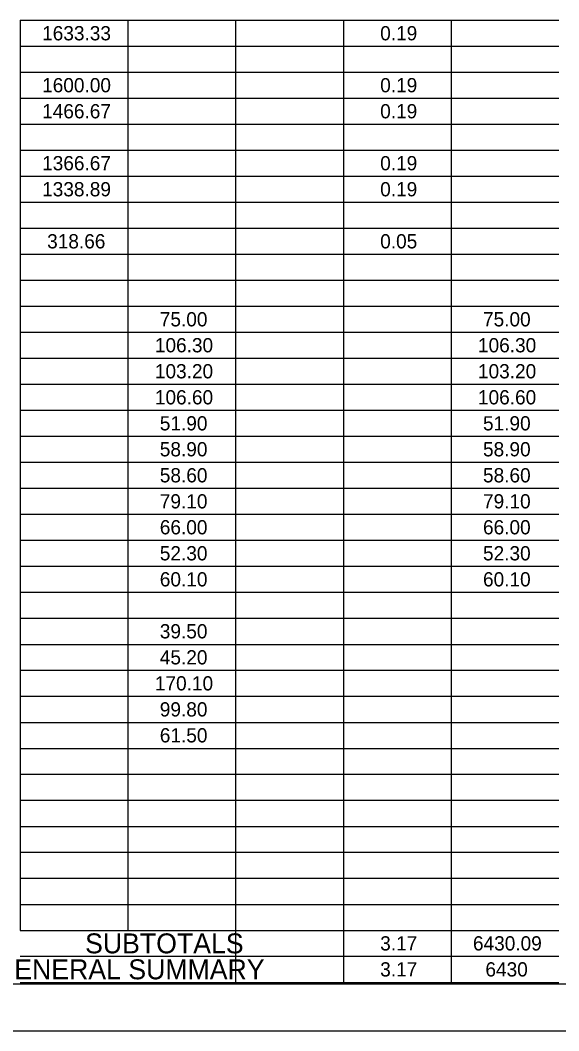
# Model space of a CAD drawing. Extents: x 0 to 34, y 0 to 22.
# Drawn here: x 10.58 to 16.38, y 0 to 10.87 of the extents above; entities that cross this region are included whole.
import ezdxf

# ---------------------------------------------------------------- set-up
doc = ezdxf.new("R2010")
doc.units = 0
for name, color, linetype in [('SH_Border', 7, 'Continuous'), ('SH_Cut_Line', 7, 'Continuous'), ('SH_Text', 7, 'Continuous')]:
    doc.layers.add(name, color=color, linetype=linetype)

msp = doc.modelspace()

# ---------------------------------------------------------------- linework, layer by layer
at = {"layer": 'SH_Border'}
msp.add_lwpolyline([(1.5, 21.5), (33.5, 21.5), (33.5, 0.5), (1.5, 0.5)], close=True, dxfattribs=at)
at = {"layer": 'SH_Cut_Line'}
msp.add_lwpolyline([(0, 0), (34, 0), (34, 22), (0, 22)], close=True, dxfattribs=at)
at = {"layer": 'SH_Text'}
for p, q in [((10.584, 10.871), (11.743, 10.871)), ((10.584, 10.871), (10.584, 10.591)), ((11.743, 10.871), (14.061, 10.871)), ((11.743, 10.871), (11.743, 10.591)), ((12.902, 10.871), (12.902, 10.591)), ((14.061, 10.871), (15.22, 10.871)), ((14.061, 10.871), (14.061, 10.591)), ((15.22, 10.871), (16.378, 10.871)), ((15.22, 10.871), (15.22, 10.591)), ((10.584, 10.591), (11.743, 10.591)), ((10.584, 10.591), (10.584, 10.311)), ((11.743, 10.591), (14.061, 10.591)), ((11.743, 10.591), (11.743, 10.311)), ((12.902, 10.591), (12.902, 10.311)), ((14.061, 10.591), (15.22, 10.591)), ((14.061, 10.591), (14.061, 10.311)), ((15.22, 10.591), (16.378, 10.591)), ((15.22, 10.591), (15.22, 10.311)), ((10.584, 10.311), (11.743, 10.311)), ((10.584, 10.311), (10.584, 10.031)), ((11.743, 10.311), (14.061, 10.311)), ((11.743, 10.311), (11.743, 10.031)), ((12.902, 10.311), (12.902, 10.031)), ((14.061, 10.311), (15.22, 10.311)), ((14.061, 10.311), (14.061, 10.031)), ((15.22, 10.311), (16.378, 10.311)), ((15.22, 10.311), (15.22, 10.031)), ((10.584, 10.031), (11.743, 10.031)), ((10.584, 10.031), (10.584, 9.752)), ((11.743, 10.031), (14.061, 10.031)), ((11.743, 10.031), (11.743, 9.752)), ((12.902, 10.031), (12.902, 9.752)), ((14.061, 10.031), (15.22, 10.031)), ((14.061, 10.031), (14.061, 9.752)), ((15.22, 10.031), (16.378, 10.031)), ((15.22, 10.031), (15.22, 9.752)), ((10.584, 9.752), (11.743, 9.752)), ((10.584, 9.752), (10.584, 9.472)), ((11.743, 9.752), (14.061, 9.752)), ((11.743, 9.752), (11.743, 9.472)), ((12.902, 9.752), (12.902, 9.472)), ((14.061, 9.752), (15.22, 9.752)), ((14.061, 9.752), (14.061, 9.472)), ((15.22, 9.752), (16.378, 9.752)), ((15.22, 9.752), (15.22, 9.472)), ((10.584, 9.472), (11.743, 9.472)), ((10.584, 9.472), (10.584, 9.192)), ((11.743, 9.472), (14.061, 9.472)), ((11.743, 9.472), (11.743, 9.192)), ((12.902, 9.472), (12.902, 9.192)), ((14.061, 9.472), (15.22, 9.472)), ((14.061, 9.472), (14.061, 9.192)), ((15.22, 9.472), (16.378, 9.472)), ((15.22, 9.472), (15.22, 9.192)), ((10.584, 9.192), (11.743, 9.192)), ((10.584, 9.192), (10.584, 8.913)), ((11.743, 9.192), (14.061, 9.192)), ((11.743, 9.192), (11.743, 8.913)), ((12.902, 9.192), (12.902, 8.913)), ((14.061, 9.192), (15.22, 9.192)), ((14.061, 9.192), (14.061, 8.913)), ((15.22, 9.192), (16.378, 9.192)), ((15.22, 9.192), (15.22, 8.913)), ((10.584, 8.913), (11.743, 8.913)), ((10.584, 8.913), (10.584, 8.633)), ((11.743, 8.913), (14.061, 8.913)), ((11.743, 8.913), (11.743, 8.633)), ((12.902, 8.913), (12.902, 8.633)), ((14.061, 8.913), (15.22, 8.913)), ((14.061, 8.913), (14.061, 8.633)), ((15.22, 8.913), (16.378, 8.913)), ((15.22, 8.913), (15.22, 8.633)), ((10.584, 8.633), (11.743, 8.633)), ((10.584, 8.633), (10.584, 8.353)), ((11.743, 8.633), (14.061, 8.633)), ((11.743, 8.633), (11.743, 8.353)), ((12.902, 8.633), (12.902, 8.353)), ((14.061, 8.633), (15.22, 8.633)), ((14.061, 8.633), (14.061, 8.353)), ((15.22, 8.633), (16.378, 8.633)), ((15.22, 8.633), (15.22, 8.353)), ((10.584, 8.353), (11.743, 8.353)), ((10.584, 8.353), (10.584, 8.073)), ((11.743, 8.353), (14.061, 8.353)), ((11.743, 8.353), (11.743, 8.073)), ((12.902, 8.353), (12.902, 8.073)), ((14.061, 8.353), (15.22, 8.353)), ((14.061, 8.353), (14.061, 8.073)), ((15.22, 8.353), (16.378, 8.353)), ((15.22, 8.353), (15.22, 8.073)), ((10.584, 8.073), (11.743, 8.073)), ((10.584, 8.073), (10.584, 7.794)), ((11.743, 8.073), (14.061, 8.073)), ((11.743, 8.073), (11.743, 7.794)), ((12.902, 8.073), (12.902, 7.794)), ((14.061, 8.073), (15.22, 8.073)), ((14.061, 8.073), (14.061, 7.794)), ((15.22, 8.073), (16.378, 8.073)), ((15.22, 8.073), (15.22, 7.794)), ((10.584, 7.794), (11.743, 7.794)), ((10.584, 7.794), (10.584, 7.514)), ((11.743, 7.794), (14.061, 7.794)), ((11.743, 7.794), (11.743, 7.514)), ((12.902, 7.794), (12.902, 7.514)), ((14.061, 7.794), (15.22, 7.794)), ((14.061, 7.794), (14.061, 7.514)), ((15.22, 7.794), (16.378, 7.794)), ((15.22, 7.794), (15.22, 7.514)), ((10.584, 7.514), (11.743, 7.514)), ((10.584, 7.514), (10.584, 7.234)), ((11.743, 7.514), (14.061, 7.514)), ((11.743, 7.514), (11.743, 7.234)), ((12.902, 7.514), (12.902, 7.234)), ((14.061, 7.514), (15.22, 7.514)), ((14.061, 7.514), (14.061, 7.234)), ((15.22, 7.514), (16.378, 7.514)), ((15.22, 7.514), (15.22, 7.234)), ((10.584, 7.234), (11.743, 7.234)), ((10.584, 7.234), (10.584, 6.955)), ((11.743, 7.234), (14.061, 7.234)), ((11.743, 7.234), (11.743, 6.955)), ((12.902, 7.234), (12.902, 6.955)), ((14.061, 7.234), (15.22, 7.234)), ((14.061, 7.234), (14.061, 6.955)), ((15.22, 7.234), (16.378, 7.234)), ((15.22, 7.234), (15.22, 6.955)), ((10.584, 6.955), (11.743, 6.955)), ((10.584, 6.955), (10.584, 6.675)), ((11.743, 6.955), (14.061, 6.955)), ((11.743, 6.955), (11.743, 6.675)), ((12.902, 6.955), (12.902, 6.675)), ((14.061, 6.955), (15.22, 6.955)), ((14.061, 6.955), (14.061, 6.675)), ((15.22, 6.955), (16.378, 6.955)), ((15.22, 6.955), (15.22, 6.675)), ((10.584, 6.675), (11.743, 6.675)), ((10.584, 6.675), (10.584, 6.395)), ((11.743, 6.675), (14.061, 6.675)), ((11.743, 6.675), (11.743, 6.395)), ((12.902, 6.675), (12.902, 6.395)), ((14.061, 6.675), (15.22, 6.675)), ((14.061, 6.675), (14.061, 6.395)), ((15.22, 6.675), (16.378, 6.675)), ((15.22, 6.675), (15.22, 6.395)), ((10.584, 6.395), (11.743, 6.395)), ((10.584, 6.395), (10.584, 6.115)), ((11.743, 6.395), (14.061, 6.395)), ((11.743, 6.395), (11.743, 6.115)), ((12.902, 6.395), (12.902, 6.115)), ((14.061, 6.395), (15.22, 6.395)), ((14.061, 6.395), (14.061, 6.115)), ((15.22, 6.395), (16.378, 6.395)), ((15.22, 6.395), (15.22, 6.115)), ((10.584, 6.115), (11.743, 6.115)), ((10.584, 6.115), (10.584, 5.836)), ((11.743, 6.115), (14.061, 6.115)), ((11.743, 6.115), (11.743, 5.836)), ((12.902, 6.115), (12.902, 5.836)), ((14.061, 6.115), (15.22, 6.115)), ((14.061, 6.115), (14.061, 5.836)), ((15.22, 6.115), (16.378, 6.115)), ((15.22, 6.115), (15.22, 5.836)), ((10.584, 5.836), (11.743, 5.836)), ((10.584, 5.836), (10.584, 5.276)), ((11.743, 5.836), (14.061, 5.836)), ((11.743, 5.836), (11.743, 5.276)), ((12.902, 5.836), (12.902, 5.276)), ((14.061, 5.836), (15.22, 5.836)), ((14.061, 5.836), (14.061, 5.276)), ((15.22, 5.836), (16.378, 5.836)), ((15.22, 5.836), (15.22, 5.276)), ((10.584, 5.556), (11.743, 5.556)), ((11.743, 5.556), (14.061, 5.556)), ((14.061, 5.556), (15.22, 5.556)), ((15.22, 5.556), (16.378, 5.556)), ((10.584, 5.276), (11.743, 5.276)), ((10.584, 5.276), (10.584, 4.997)), ((11.743, 5.276), (14.061, 5.276)), ((11.743, 5.276), (11.743, 4.997)), ((12.902, 5.276), (12.902, 4.997)), ((14.061, 5.276), (15.22, 5.276)), ((14.061, 5.276), (14.061, 4.997)), ((15.22, 5.276), (16.378, 5.276)), ((15.22, 5.276), (15.22, 4.997)), ((10.584, 4.997), (11.743, 4.997)), ((10.584, 4.997), (10.584, 4.717)), ((11.743, 4.997), (14.061, 4.997)), ((11.743, 4.997), (11.743, 4.717)), ((12.902, 4.997), (12.902, 4.717)), ((14.061, 4.997), (15.22, 4.997)), ((14.061, 4.997), (14.061, 4.717)), ((15.22, 4.997), (16.378, 4.997)), ((15.22, 4.997), (15.22, 4.717)), ((10.584, 4.717), (11.743, 4.717)), ((10.584, 4.717), (10.584, 4.437)), ((11.743, 4.717), (14.061, 4.717)), ((11.743, 4.717), (11.743, 4.437)), ((12.902, 4.717), (12.902, 4.437)), ((14.061, 4.717), (15.22, 4.717)), ((14.061, 4.717), (14.061, 4.437)), ((15.22, 4.717), (16.378, 4.717)), ((15.22, 4.717), (15.22, 4.437)), ((10.584, 4.437), (11.743, 4.437)), ((10.584, 4.437), (10.584, 3.878)), ((11.743, 4.437), (14.061, 4.437)), ((11.743, 4.437), (11.743, 3.878)), ((12.902, 4.437), (12.902, 3.878)), ((14.061, 4.437), (15.22, 4.437)), ((14.061, 4.437), (14.061, 3.878)), ((15.22, 4.437), (16.378, 4.437)), ((15.22, 4.437), (15.22, 3.878)), ((10.584, 4.157), (11.743, 4.157)), ((11.743, 4.157), (14.061, 4.157)), ((14.061, 4.157), (15.22, 4.157)), ((15.22, 4.157), (16.378, 4.157)), ((10.584, 3.878), (11.743, 3.878)), ((10.584, 3.878), (10.584, 3.598)), ((11.743, 3.878), (14.061, 3.878)), ((11.743, 3.878), (11.743, 3.598)), ((12.902, 3.878), (12.902, 3.598)), ((14.061, 3.878), (15.22, 3.878)), ((14.061, 3.878), (14.061, 3.598)), ((15.22, 3.878), (16.378, 3.878)), ((15.22, 3.878), (15.22, 3.598)), ((10.584, 3.598), (11.743, 3.598)), ((10.584, 3.598), (10.584, 3.318)), ((11.743, 3.598), (14.061, 3.598)), ((11.743, 3.598), (11.743, 3.318)), ((12.902, 3.598), (12.902, 3.318)), ((14.061, 3.598), (15.22, 3.598)), ((14.061, 3.598), (14.061, 3.318)), ((15.22, 3.598), (16.378, 3.598)), ((15.22, 3.598), (15.22, 3.318)), ((10.584, 3.318), (11.743, 3.318)), ((10.584, 3.318), (10.584, 3.038)), ((11.743, 3.318), (14.061, 3.318)), ((11.743, 3.318), (11.743, 3.038)), ((12.902, 3.318), (12.902, 3.038)), ((14.061, 3.318), (15.22, 3.318)), ((14.061, 3.318), (14.061, 3.038)), ((15.22, 3.318), (16.378, 3.318)), ((15.22, 3.318), (15.22, 3.038)), ((10.584, 3.038), (11.743, 3.038)), ((10.584, 3.038), (10.584, 2.479)), ((11.743, 3.038), (14.061, 3.038)), ((11.743, 3.038), (11.743, 2.479)), ((12.902, 3.038), (12.902, 2.479)), ((14.061, 3.038), (15.22, 3.038)), ((14.061, 3.038), (14.061, 2.479)), ((15.22, 3.038), (16.378, 3.038)), ((15.22, 3.038), (15.22, 2.479)), ((10.584, 2.759), (11.743, 2.759)), ((11.743, 2.759), (14.061, 2.759)), ((14.061, 2.759), (15.22, 2.759)), ((15.22, 2.759), (16.378, 2.759)), ((10.584, 2.479), (11.743, 2.479)), ((10.584, 2.479), (10.584, 2.199)), ((11.743, 2.479), (14.061, 2.479)), ((11.743, 2.479), (11.743, 2.199)), ((12.902, 2.479), (12.902, 2.199)), ((14.061, 2.479), (15.22, 2.479)), ((14.061, 2.479), (14.061, 2.199)), ((15.22, 2.479), (16.378, 2.479)), ((15.22, 2.479), (15.22, 2.199)), ((10.584, 2.199), (11.743, 2.199)), ((10.584, 2.199), (10.584, 1.92)), ((11.743, 2.199), (14.061, 2.199)), ((11.743, 2.199), (11.743, 1.92)), ((12.902, 2.199), (12.902, 1.92)), ((14.061, 2.199), (15.22, 2.199)), ((14.061, 2.199), (14.061, 1.92)), ((15.22, 2.199), (16.378, 2.199)), ((15.22, 2.199), (15.22, 1.92)), ((10.584, 1.92), (11.743, 1.92)), ((10.584, 1.92), (10.584, 1.64)), ((11.743, 1.92), (14.061, 1.92)), ((11.743, 1.92), (11.743, 1.64)), ((12.902, 1.92), (12.902, 1.64)), ((14.061, 1.92), (15.22, 1.92)), ((14.061, 1.92), (14.061, 1.64)), ((15.22, 1.92), (16.378, 1.92)), ((15.22, 1.92), (15.22, 1.64)), ((10.584, 1.64), (11.743, 1.64)), ((10.584, 1.64), (10.584, 1.08)), ((11.743, 1.64), (14.061, 1.64)), ((11.743, 1.64), (11.743, 1.08)), ((12.902, 1.64), (12.902, 1.08)), ((14.061, 1.64), (15.22, 1.64)), ((14.061, 1.64), (14.061, 1.08)), ((15.22, 1.64), (16.378, 1.64)), ((15.22, 1.64), (15.22, 1.08)), ((10.584, 1.36), (11.743, 1.36)), ((11.743, 1.36), (14.061, 1.36)), ((14.061, 1.36), (15.22, 1.36)), ((15.22, 1.36), (16.378, 1.36)), ((10.584, 1.08), (11.743, 1.08)), ((11.743, 1.08), (14.061, 1.08)), ((12.902, 1.08), (12.902, 0.801)), ((14.061, 1.08), (15.22, 1.08)), ((14.061, 1.08), (14.061, 0.801)), ((15.22, 1.08), (16.378, 1.08)), ((15.22, 1.08), (15.22, 0.801)), ((10.584, 0.801), (11.743, 0.801)), ((11.743, 0.801), (14.061, 0.801)), ((12.902, 0.801), (12.902, 0.521)), ((14.061, 0.801), (15.22, 0.801)), ((14.061, 0.801), (14.061, 0.521)), ((15.22, 0.801), (16.378, 0.801)), ((15.22, 0.801), (15.22, 0.521)), ((10.584, 0.521), (11.743, 0.521)), ((11.743, 0.521), (14.061, 0.521)), ((14.061, 0.521), (15.22, 0.521)), ((15.22, 0.521), (16.378, 0.521))]:
    msp.add_line(p, q, dxfattribs=at)

# ---------------------------------------------------------------- texts
for s, height, p in [('1633.33', 0.1532, (10.82, 10.654)), ('0.19', 0.1532, (14.457, 10.654)), ('1600.00', 0.1532, (10.82, 10.095)), ('0.19', 0.1532, (14.457, 10.095)), ('1466.67', 0.1532, (10.82, 9.815)), ('0.19', 0.1532, (14.457, 9.815)), ('1366.67', 0.1532, (10.82, 9.256)), ('0.19', 0.1532, (14.457, 9.256)), ('1338.89', 0.1532, (10.82, 8.976)), ('0.19', 0.1532, (14.457, 8.976)), ('318.66', 0.1532, (10.874, 8.416)), ('0.05', 0.1532, (14.457, 8.416)), ('75.00', 0.1532, (12.086, 7.577)), ('75.00', 0.1532, (15.563, 7.577)), ('106.30', 0.1532, (12.033, 7.298)), ('106.30', 0.1532, (15.509, 7.298)), ('103.20', 0.1532, (12.033, 7.018)), ('103.20', 0.1532, (15.509, 7.018)), ('106.60', 0.1532, (12.033, 6.738)), ('106.60', 0.1532, (15.509, 6.738)), ('51.90', 0.1532, (12.086, 6.458)), ('51.90', 0.1532, (15.563, 6.458)), ('58.90', 0.1532, (12.086, 6.179)), ('58.90', 0.1532, (15.563, 6.179)), ('58.60', 0.1532, (12.086, 5.899)), ('58.60', 0.1532, (15.563, 5.899)), ('79.10', 0.1532, (12.086, 5.619)), ('79.10', 0.1532, (15.563, 5.619)), ('66.00', 0.1532, (12.086, 5.34)), ('66.00', 0.1532, (15.563, 5.34)), ('52.30', 0.1532, (12.086, 5.06)), ('52.30', 0.1532, (15.563, 5.06)), ('60.10', 0.1532, (12.086, 4.78)), ('60.10', 0.1532, (15.563, 4.78)), ('39.50', 0.1532, (12.086, 4.221)), ('45.20', 0.1532, (12.086, 3.941)), ('170.10', 0.1532, (12.033, 3.661)), ('99.80', 0.1532, (12.086, 3.381)), ('61.50', 0.1532, (12.086, 3.102)), ('SUBTOTALS', 0.2145, (11.282, 0.833)), ('3.17', 0.1532, (14.457, 0.864)), ('6430.09', 0.1532, (15.455, 0.864)), ('TOTALS CARRIED TO GENERAL SUMMARY', 0.21445, (7.254, 0.554)), ('3.17', 0.1532, (14.457, 0.584)), ('6430', 0.1532, (15.589, 0.584))]:
    msp.add_text(s, height=height, dxfattribs=at).set_placement(p)

doc.saveas('drawing.dxf')
